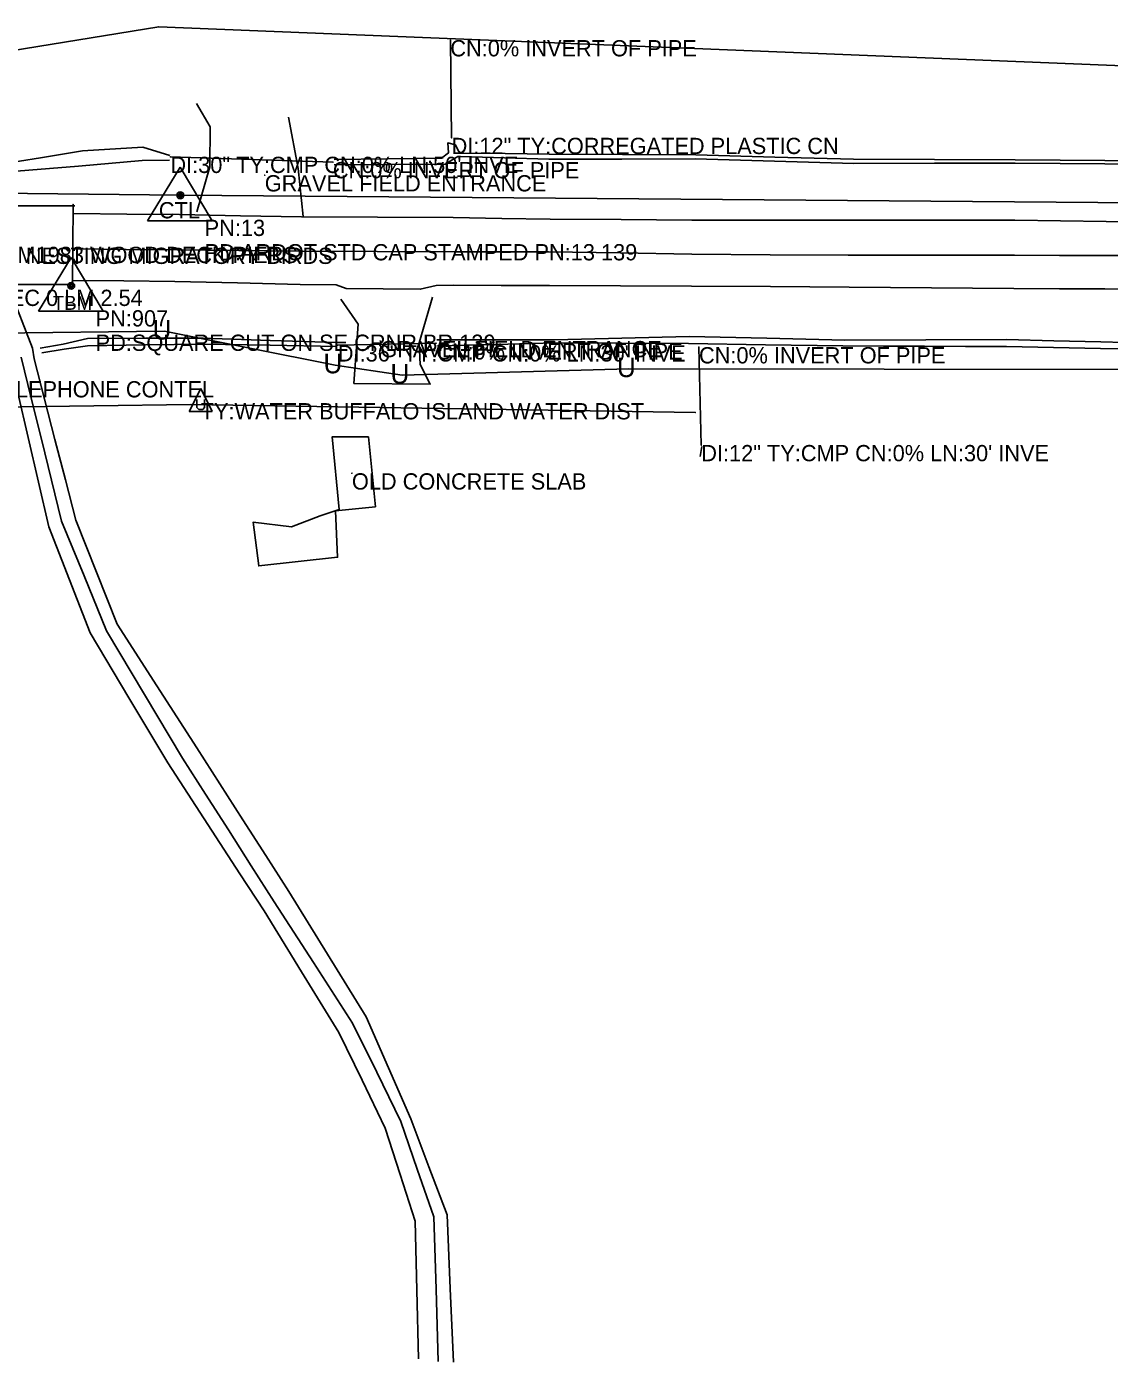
# Model space of a CAD drawing. Extents: x 1810987 to 1814397, y 533216 to 533930.
# Drawn here: x 1812536.5 to 1812869.4, y 533215.9 to 533626.5 of the extents above; entities that cross this region are included whole.
import ezdxf

# ---------------------------------------------------------------- set-up
doc = ezdxf.new("R2010")
doc.units = 0
for name, color, linetype in [('Default', 7, 'Continuous'), ('S_BASELINE', 7, 'Continuous'), ('S_BRIDGE', 7, 'Continuous'), ('S_DITCHLINE', 7, 'Continuous'), ('S_DRG_PT_SYM', 7, 'Continuous'), ('S_DRIVEWAY', 7, 'Continuous'), ('S_EDGE_CONCRETE', 7, 'Continuous'), ('S_EDGE_PAVEMENT', 7, 'Continuous'), ('S_GAS_UTILITIES', 7, 'Continuous'), ('S_LOG_MILE_ANNOT', 7, 'Continuous'), ('S_MSC_PT_SYM', 7, 'Continuous'), ('S_PAVEMENT_CROWN', 7, 'Continuous'), ('S_PRIMARY_CTL', 7, 'Continuous'), ('S_PRIMARY_CTL_ANNOT', 7, 'Continuous'), ('S_SIDE_DRAIN', 7, 'Continuous'), ('S_SIDE_DRAIN_ANNOT', 7, 'Continuous'), ('S_STR_PT_SYM', 7, 'Continuous'), ('S_STREAM', 7, 'Continuous'), ('S_SURVEY_TEXT_ANNOT', 7, 'Continuous'), ('S_UNDERGROUND_CABLE', 7, 'Continuous'), ('S_UTILITY_POLE_ANNOT', 7, 'Continuous'), ('S_UTL_PT_SYM', 7, 'Continuous'), ('S_WATER_UTILITIES', 7, 'Continuous')]:
    doc.layers.add(name, color=color, linetype=linetype)

msp = doc.modelspace()

# ---------------------------------------------------------------- linework, layer by layer
at = {"layer": 'S_BASELINE'}
for p, q in [((1811772.1, 533584), (1812583.73, 533574.67)), ((1812583.73, 533574.67), (1813453.08, 533567.94))]:
    msp.add_line(p, q, dxfattribs=at)
at = {"layer": 'S_BRIDGE'}
for p, q in [((1812550.77, 533571.41), (1812504.44, 533571.5)), ((1812550.61, 533547.27), (1812550.77, 533571.41)), ((1812504.58, 533547.28), (1812550.61, 533547.27))]:
    msp.add_line(p, q, dxfattribs=at)
at = {"layer": 'S_DITCHLINE'}
for points in [[(1812527.72, 533584.11), (1812540.72, 533586.23), (1812553.71, 533588.36), (1812572.17, 533589.51), (1812580.52, 533586.92)], [(1812631, 533585.7), (1812647.52, 533585.87), (1812664.04, 533586.04), (1812666.2, 533587.72), (1812665.99, 533590.78), (1812668.34, 533590.23), (1812669.31, 533588.22), (1812670.14, 533587.63), (1812683.64, 533587.5), (1812697.15, 533587.37), (1812719.7, 533587.23), (1812742.26, 533587.09), (1812766.52, 533586.43), (1812790.78, 533585.78), (1812815.61, 533585.7), (1812840.45, 533585.62), (1812854.25, 533585.49), (1812868.04, 533585.36), (1812881.84, 533585.23)], [(1812528.11, 533581.69), (1812552.45, 533583.6), (1812572.02, 533585.33), (1812580.46, 533585.45)], [(1812631.07, 533584.01), (1812648.12, 533584.12), (1812665.17, 533584.23), (1812669.07, 533586.6), (1812669.87, 533586.64), (1812683.45, 533586.2), (1812697.04, 533585.76), (1812719.55, 533585.8), (1812742.06, 533585.84), (1812766.46, 533585.15), (1812790.87, 533584.46), (1812815.65, 533584.52), (1812840.43, 533584.58), (1812854.24, 533584.46), (1812868.05, 533584.34), (1812881.86, 533584.23)], [(1812540.68, 533527.66), (1812547.7, 533528.96), (1812555.2, 533530.65), (1812573.01, 533530.71), (1812590.81, 533530.76), (1812611.38, 533530.07), (1812631.95, 533529.38)], [(1812662.62, 533530.23), (1812680.72, 533530.21), (1812698.82, 533530.2), (1812719.51, 533530.74), (1812740.2, 533531.29), (1812764.12, 533530.73), (1812788.04, 533530.17), (1812812.95, 533530.24), (1812837.86, 533530.31), (1812852.35, 533529.95), (1812866.84, 533529.6), (1812881.34, 533529.24)], [(1812541.17, 533526.22), (1812548.06, 533527.39), (1812555.25, 533528.43), (1812573.01, 533528.68), (1812590.77, 533528.93), (1812611.36, 533528.58), (1812631.95, 533528.23)], [(1812662.84, 533528.39), (1812680.88, 533528.84), (1812698.93, 533529.29), (1812719.46, 533529.19), (1812739.99, 533529.08), (1812763.7, 533528.72), (1812787.41, 533528.36), (1812800.01, 533528.31), (1812812.61, 533528.25), (1812825.21, 533528.2), (1812837.81, 533528.15), (1812852.25, 533527.88), (1812866.69, 533527.61), (1812881.13, 533527.34)], [(1812744.06, 533497.5), (1812743.57, 533494.4)]]:
    msp.add_lwpolyline(points, dxfattribs=at)
at = {"layer": 'S_DRG_PT_SYM'}
for points in [[(1812666.77, 533622.38), (1812666.77, 533622.43), (1812666.77, 533622.38), (1812666.72, 533622.38), (1812666.77, 533622.38), (1812666.77, 533622.33), (1812666.77, 533622.38), (1812666.82, 533622.38)], [(1812667.16, 533592.35), (1812667.16, 533592.4), (1812667.16, 533592.35), (1812667.11, 533592.35), (1812667.16, 533592.35), (1812667.16, 533592.3), (1812667.16, 533592.35), (1812667.21, 533592.35)], [(1812580.7, 533586.53), (1812580.7, 533586.58), (1812580.7, 533586.53), (1812580.65, 533586.53), (1812580.7, 533586.53), (1812580.7, 533586.48), (1812580.7, 533586.53), (1812580.75, 533586.53)], [(1812630.65, 533584.9), (1812630.65, 533584.95), (1812630.65, 533584.9), (1812630.6, 533584.9), (1812630.65, 533584.9), (1812630.65, 533584.85), (1812630.65, 533584.9), (1812630.7, 533584.9)], [(1812632.17, 533528.58), (1812632.17, 533528.63), (1812632.17, 533528.58), (1812632.12, 533528.58), (1812632.17, 533528.58), (1812632.17, 533528.53), (1812632.17, 533528.58), (1812632.22, 533528.58)], [(1812662.4, 533529.17), (1812662.4, 533529.22), (1812662.4, 533529.17), (1812662.35, 533529.17), (1812662.4, 533529.17), (1812662.4, 533529.12), (1812662.4, 533529.17), (1812662.45, 533529.17)], [(1812743.23, 533527.99), (1812743.23, 533528.04), (1812743.23, 533527.99), (1812743.18, 533527.99), (1812743.23, 533527.99), (1812743.23, 533527.94), (1812743.23, 533527.99), (1812743.28, 533527.99)], [(1812743.93, 533497.91), (1812743.93, 533497.96), (1812743.93, 533497.91), (1812743.88, 533497.91), (1812743.93, 533497.91), (1812743.93, 533497.86), (1812743.93, 533497.91), (1812743.98, 533497.91)]]:
    msp.add_lwpolyline(points, dxfattribs=at)
at = {"layer": 'S_DRIVEWAY'}
for points in [[(1812588.8, 533569.6), (1812592.79, 533583.38), (1812592.95, 533595.69), (1812588.74, 533602.91)], [(1812617.03, 533598.7), (1812620.01, 533582.95), (1812621.55, 533568.17)], [(1812633.11, 533542.77), (1812638.43, 533535.03), (1812637.11, 533516.87), (1812660.6, 533516.63), (1812657.53, 533522.62), (1812657.18, 533529.36), (1812661.24, 533543.33)]]:
    msp.add_lwpolyline(points, dxfattribs=at)
at = {"layer": 'S_EDGE_CONCRETE'}
msp.add_lwpolyline([(1812641.58, 533500.47), (1812643.75, 533478.95), (1812631.47, 533477.68), (1812632.09, 533463.41), (1812607.86, 533460.76), (1812606.12, 533474.14), (1812617.9, 533472.79), (1812626.71, 533476.17), (1812632.56, 533478.07), (1812630.43, 533500.42)], close=True, dxfattribs=at)
at = {"layer": 'S_EDGE_PAVEMENT'}
for points in [[(1812551, 533569.04), (1812567.26, 533568.92), (1812583.53, 533568.79), (1812602.27, 533568.41), (1812621.01, 533568.02), (1812644.35, 533567.94), (1812667.69, 533567.86), (1812682.59, 533567.59), (1812697.49, 533567.31), (1812719.28, 533567.19), (1812741.07, 533567.06), (1812765.58, 533567.02), (1812790.1, 533566.98), (1812802.65, 533566.99), (1812815.21, 533566.99), (1812827.77, 533567), (1812840.32, 533567.01), (1812854.39, 533566.82), (1812868.46, 533566.63), (1812882.53, 533566.44)], [(1812550.75, 533548.5), (1812566.4, 533548.35), (1812582.06, 533548.21), (1812601.33, 533547.73), (1812620.61, 533547.26), (1812631.63, 533547.13), (1812634.77, 533545.98), (1812657.53, 533545.77), (1812662.45, 533546.94), (1812667.6, 533547.02), (1812682.45, 533546.97), (1812697.3, 533546.91), (1812719.12, 533546.84), (1812740.93, 533546.77), (1812765.19, 533546.59), (1812789.45, 533546.4), (1812802.09, 533546.29), (1812814.74, 533546.19), (1812827.38, 533546.08), (1812840.02, 533545.98), (1812854.03, 533545.92), (1812868.04, 533545.87), (1812882.05, 533545.81)]]:
    msp.add_lwpolyline(points, dxfattribs=at)
at = {"layer": 'S_GAS_UTILITIES'}
for p, q in [((1812392.73, 533596.39), (1812577.11, 533626.45)), ((1812577.11, 533626.45), (1813438.99, 533591.71))]:
    msp.add_line(p, q, dxfattribs=at)
at = {"layer": 'S_MSC_PT_SYM'}
for points in [[(1812609.72, 533580.86), (1812609.72, 533580.91), (1812609.72, 533580.86), (1812609.67, 533580.86), (1812609.72, 533580.86), (1812609.72, 533580.81), (1812609.72, 533580.86), (1812609.77, 533580.86)], [(1812645.22, 533529.88), (1812645.22, 533529.93), (1812645.22, 533529.88), (1812645.17, 533529.88), (1812645.22, 533529.88), (1812645.22, 533529.83), (1812645.22, 533529.88), (1812645.27, 533529.88)], [(1812636.51, 533489.22), (1812636.51, 533489.27), (1812636.51, 533489.22), (1812636.46, 533489.22), (1812636.51, 533489.22), (1812636.51, 533489.17), (1812636.51, 533489.22), (1812636.56, 533489.22)]]:
    msp.add_lwpolyline(points, dxfattribs=at)
at = {"layer": 'S_PAVEMENT_CROWN'}
msp.add_lwpolyline([(1812551.09, 533558.21), (1812567.09, 533558.05), (1812583.08, 533557.88), (1812601.73, 533557.71), (1812620.37, 533557.55), (1812644.29, 533557.41), (1812668.2, 533557.27), (1812682.57, 533557.3), (1812696.94, 533557.33), (1812718.98, 533556.97), (1812741.03, 533556.61), (1812765.08, 533556.42), (1812789.14, 533556.22), (1812801.91, 533556.22), (1812814.69, 533556.22), (1812827.47, 533556.23), (1812840.25, 533556.23), (1812854.04, 533556.2), (1812867.82, 533556.16), (1812881.61, 533556.13)], dxfattribs=at)
at = {"layer": 'S_PRIMARY_CTL'}
for p, q in [((1812583.73, 533583.37), (1812573.7, 533566.86)), ((1812583.73, 533583.37), (1812593.56, 533566.86)), ((1812573.7, 533566.86), (1812593.56, 533566.86)), ((1812550.2, 533555.55), (1812540.17, 533539.03)), ((1812550.2, 533555.55), (1812560.03, 533539.03)), ((1812540.17, 533539.03), (1812560.03, 533539.03))]:
    msp.add_line(p, q, dxfattribs=at)
for centre, radius in [((1812583.73, 533574.67), 1.04), ((1812583.73, 533574.67), 0.609), ((1812583.73, 533574.67), 0.344), ((1812550.2, 533546.85), 1.04), ((1812550.2, 533546.85), 0.609), ((1812550.2, 533546.85), 0.344)]:
    msp.add_circle(centre, radius, dxfattribs=at)
at = {"layer": 'S_SIDE_DRAIN'}
for p, q in [((1812667.16, 533592.35), (1812666.77, 533622.38)), ((1812580.7, 533586.53), (1812630.65, 533584.9)), ((1812632.17, 533528.58), (1812662.4, 533529.17)), ((1812743.93, 533497.91), (1812743.23, 533527.99))]:
    msp.add_line(p, q, dxfattribs=at)
at = {"layer": 'S_STR_PT_SYM'}
for points in [[(1812550.77, 533571.41), (1812550.77, 533571.91), (1812550.77, 533571.41), (1812550.27, 533571.41), (1812550.77, 533571.41), (1812550.77, 533570.91), (1812550.77, 533571.41), (1812551.27, 533571.41)], [(1812550.61, 533547.27), (1812550.61, 533547.77), (1812550.61, 533547.27), (1812550.11, 533547.27), (1812550.61, 533547.27), (1812550.61, 533546.77), (1812550.61, 533547.27), (1812551.11, 533547.27)]]:
    msp.add_lwpolyline(points, dxfattribs=at)
at = {"layer": 'S_STREAM'}
for points in [[(1812531.25, 533545.9), (1812538.27, 533527.71), (1812538.76, 533524.43), (1812541.97, 533512.01), (1812545.18, 533499.6), (1812548.39, 533487.19), (1812551.61, 533474.78), (1812557.94, 533458.82), (1812564.28, 533442.86), (1812576.55, 533423.85), (1812588.82, 533404.85), (1812595.9, 533393.79), (1812602.99, 533382.73), (1812610.07, 533371.67), (1812617.16, 533360.61), (1812629.01, 533341.38), (1812640.86, 533322.16), (1812647.74, 533306.45), (1812654.62, 533290.73), (1812660.2, 533275.97), (1812665.79, 533261.21), (1812666.76, 533238.57), (1812667.74, 533215.93)], [(1812534.8, 533524.89), (1812537.9, 533512.3), (1812541.01, 533499.71), (1812544.12, 533487.12), (1812547.23, 533474.52), (1812554.15, 533457.65), (1812561.06, 533440.77), (1812572.75, 533421.21), (1812584.44, 533401.65), (1812591.47, 533390.61), (1812598.51, 533379.57), (1812605.54, 533368.54), (1812612.58, 533357.5), (1812624.65, 533338.84), (1812636.73, 533320.18), (1812644.12, 533305.07), (1812651.51, 533289.97), (1812656.59, 533275.29), (1812661.67, 533260.62), (1812662.37, 533238.39), (1812663.07, 533216.15)], [(1812533.76, 533513.93), (1812536.94, 533500.19), (1812540.13, 533486.46), (1812543.31, 533472.73), (1812549.66, 533456.43), (1812556.01, 533440.13), (1812567.95, 533420.19), (1812579.89, 533400.25), (1812587.29, 533388.86), (1812594.69, 533377.47), (1812602.09, 533366.08), (1812609.49, 533354.69), (1812621.01, 533336), (1812632.52, 533317.31), (1812639.62, 533302.61), (1812646.71, 533287.9), (1812651.33, 533273.61), (1812655.95, 533259.32), (1812656.45, 533238.14), (1812656.95, 533216.96)]]:
    msp.add_lwpolyline(points, dxfattribs=at)
at = {"layer": 'S_UNDERGROUND_CABLE'}
for p, q in [((1812438.75, 533531.19), (1812578.83, 533532.86)), ((1812578.83, 533532.86), (1812631.39, 533522.5)), ((1812631.39, 533522.5), (1812651.99, 533519.34)), ((1812651.99, 533519.34), (1812721.63, 533521.34)), ((1812721.63, 533521.34), (1812891.21, 533521.11)), ((1812590.01, 533515.32), (1812586.49, 533508.23)), ((1812590.01, 533515.32), (1812593.5, 533508.23)), ((1812588.81, 533509.47), (1812588.81, 533511.91)), ((1812589.43, 533508.81), (1812588.81, 533509.47)), ((1812591.18, 533509.47), (1812590.63, 533508.81)), ((1812591.18, 533511.91), (1812591.18, 533509.47)), ((1812586.49, 533508.23), (1812593.5, 533508.23)), ((1812590.63, 533508.81), (1812589.43, 533508.81))]:
    msp.add_line(p, q, dxfattribs=at)
at = {"layer": 'S_UTL_PT_SYM'}
for points in [[(1812577.11, 533626.45), (1812577.11, 533626.5), (1812577.11, 533626.45), (1812577.06, 533626.45), (1812577.11, 533626.45), (1812577.11, 533626.4), (1812577.11, 533626.45), (1812577.16, 533626.45)], [(1812586.98, 533510.34), (1812586.98, 533510.39), (1812586.98, 533510.34), (1812586.93, 533510.34), (1812586.98, 533510.34), (1812586.98, 533510.29), (1812586.98, 533510.34), (1812587.03, 533510.34)], [(1812742.08, 533507.92), (1812742.08, 533507.97), (1812742.08, 533507.92), (1812742.03, 533507.92), (1812742.08, 533507.92), (1812742.08, 533507.87), (1812742.08, 533507.92), (1812742.13, 533507.92)]]:
    msp.add_lwpolyline(points, dxfattribs=at)
at = {"layer": 'S_WATER_UTILITIES'}
for p, q in [((1812519.36, 533509.41), (1812586.98, 533510.34)), ((1812586.98, 533510.34), (1812742.08, 533507.92))]:
    msp.add_line(p, q, dxfattribs=at)

# ---------------------------------------------------------------- texts
at = {"layer": 'Default'}
for p in [(1812575.2, 533530.32), (1812627.76, 533519.95), (1812648.36, 533516.79), (1812718, 533518.79)]:
    msp.add_text('U', height=6, dxfattribs=at).set_placement(p)
at = {"layer": 'S_LOG_MILE_ANNOT'}
msp.add_text('RT 139 SEC 0 LM 2.54', height=5, dxfattribs=at).set_placement((1812503.07, 533540.65))
at = {"layer": 'S_PRIMARY_CTL'}
for s, height, p in [('CTL', 5, (1812577.14, 533567.59)), ('TBM', 4.287, (1812544.55, 533539.46))]:
    msp.add_text(s, height=height, dxfattribs=at).set_placement(p)
at = {"layer": 'S_PRIMARY_CTL_ANNOT'}
for s, p in [('PN:13', (1812591.23, 533562.17)), ('PD:ARDOT STD CAP STAMPED PN:13 139', (1812591.23, 533554.67)), ('PN:907', (1812557.7, 533534.35)), ('PD:SQUARE CUT ON SE CRNR BR 139', (1812557.7, 533526.85))]:
    msp.add_text(s, height=5, dxfattribs=at).set_placement(p)
at = {"layer": 'S_SIDE_DRAIN_ANNOT'}
for s, p in [('CN:0% INVERT OF PIPE', (1812666.77, 533617.38)), ('DI:12" TY:CORREGATED PLASTIC CN', (1812667.16, 533587.35)), ('DI:30" TY:CMP CN:0% LN:50\' INVE', (1812580.7, 533581.53)), ('CN:0% INVERT OF PIPE', (1812630.65, 533579.9)), ('DI:36" TY:CMP CN:0% LN:30\' INVE', (1812632.17, 533523.58)), ('CN:0% INVERT OF PIPE', (1812662.4, 533524.17)), ('CN:0% INVERT OF PIPE', (1812743.23, 533522.99)), ('DI:12" TY:CMP CN:0% LN:30\' INVE', (1812743.93, 533492.91))]:
    msp.add_text(s, height=5, dxfattribs=at).set_placement(p)
at = {"layer": 'S_SURVEY_TEXT_ANNOT'}
for s, p in [('GRAVEL FIELD ENTRANCE', (1812609.72, 533575.86)), ('BR M1983 WOOD DECK/PIERS', (1812522.52, 533553.85)), ('NESTING MIGRATORY BIRDS', (1812536.21, 533553.57)), ('GRAVEL FIELD ENTRANCE', (1812645.22, 533524.88)), ('OLD CONCRETE SLAB', (1812636.51, 533484.22))]:
    msp.add_text(s, height=5, dxfattribs=at).set_placement(p)
at = {"layer": 'S_UTILITY_POLE_ANNOT'}
for s, p in [('TY:TELEPHONE CONTEL', (1812514.25, 533512.54)), ('TY:WATER BUFFALO ISLAND WATER DIST', (1812590.01, 533505.78))]:
    msp.add_text(s, height=5, dxfattribs=at).set_placement(p)

doc.saveas('drawing.dxf')
